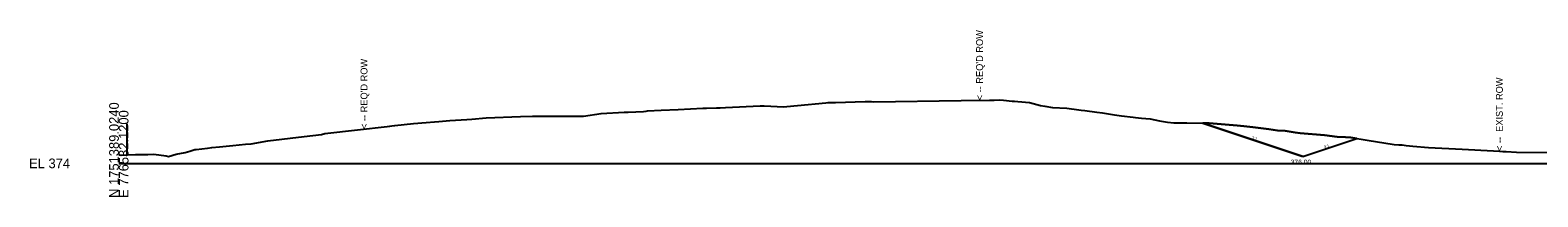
# Model space of a CAD drawing. Extents: x 776426 to 854588, y 1736205 to 1756790.
# Drawn here: x 805845.1 to 806281.9, y 1742205.1 to 1742253.4 of the extents above; entities that cross this region are included whole.
import ezdxf

# ---------------------------------------------------------------- set-up
doc = ezdxf.new("R2010")
doc.units = 0
for name, color, linetype in [('DTM CONTOURS_MAJOR_TX', 7, 'Continuous'), ('DTM_X_FLOW_ARROWS', 7, 'Continuous'), ('TRANS_EOP_PAVED', 7, 'Continuous'), ('XS_M_SHAPES_EARTHWORK', 7, 'Continuous'), ('XS_P_FINISHED_GRADE', 7, 'Continuous'), ('XS_P_ROW', 7, 'Continuous'), ('XS_P_TX_DCH', 7, 'Continuous'), ('XS_P_TX_FS_BS', 7, 'Continuous'), ('XS_X_ROW', 7, 'Continuous')]:
    doc.layers.add(name, color=color, linetype=linetype)

msp = doc.modelspace()

# ---------------------------------------------------------------- linework, layer by layer
at = {"layer": 'DTM CONTOURS_MAJOR_TX'}
msp.add_line((805870.79, 1742214.76), (806370.79, 1742214.76), dxfattribs=at)
at = {"layer": 'DTM_X_FLOW_ARROWS'}
msp.add_lwpolyline([(805870.79, 1742217.18), (805875.66, 1742217.33), (805879.19, 1742217.36), (805880.91, 1742217.4), (805884.47, 1742216.96), (805885.15, 1742216.79), (805887.37, 1742217.39), (805889.99, 1742217.89), (805891.36, 1742218.33), (805892.48, 1742218.7), (805892.78, 1742218.75), (805893.2, 1742218.8), (805896.48, 1742219.19), (805897.72, 1742219.4), (805899.96, 1742219.56), (805903.86, 1742219.95), (805907.54, 1742220.32), (805909.11, 1742220.44), (805914, 1742221.31), (805924.45, 1742222.5), (805929.49, 1742223.17), (805930.45, 1742223.38), (805939.91, 1742224.51), (805948.54, 1742225.4), (805949.34, 1742225.53), (805949.93, 1742225.59), (805950.79, 1742225.71), (805956.19, 1742226.31), (805957.45, 1742226.43), (805958.58, 1742226.5), (805963.49, 1742226.92), (805966.68, 1742227.15), (805971.61, 1742227.47), (805973.03, 1742227.54), (805977.21, 1742227.93), (805987.18, 1742228.38), (805990.64, 1742228.41), (805991.22, 1742228.41), (805991.83, 1742228.41), (805995.99, 1742228.41), (805997.85, 1742228.41), (806001.05, 1742228.4), (806005.42, 1742228.39), (806010.54, 1742229.22), (806017.2, 1742229.55), (806017.76, 1742229.58), (806018.37, 1742229.62), (806022.77, 1742229.82), (806023.56, 1742229.88), (806023.92, 1742229.96), (806027.93, 1742230.17), (806032.82, 1742230.38), (806039.99, 1742230.71), (806040.54, 1742230.73), (806041.07, 1742230.74), (806044, 1742230.84), (806045.03, 1742230.88), (806046.57, 1742230.97), (806056.6, 1742231.44), (806057.78, 1742231.43), (806063.51, 1742231.16), (806064.33, 1742231.25), (806067.44, 1742231.54), (806075.64, 1742232.31), (806076.28, 1742232.39), (806078.42, 1742232.43), (806087.04, 1742232.64), (806088.88, 1742232.65), (806089.42, 1742232.62), (806114.86, 1742232.93), (806123.1, 1742233.06), (806123.59, 1742233.08), (806124.4, 1742233.1), (806125.82, 1742233.14), (806127.11, 1742233.04), (806129.64, 1742232.82), (806130.28, 1742232.74), (806131.24, 1742232.64), (806134.67, 1742232.41), (806137.88, 1742231.57), (806139.08, 1742231.33), (806141.34, 1742230.94), (806145.45, 1742230.74), (806148.92, 1742230.3), (806149.6, 1742230.16), (806150.68, 1742230.07), (806154.14, 1742229.58), (806155.81, 1742229.36), (806159.31, 1742228.87), (806161.28, 1742228.58), (806164.73, 1742228.17), (806165.34, 1742228.09), (806167.11, 1742227.9), (806169.59, 1742227.68), (806172.29, 1742227.06), (806174.65, 1742226.69), (806176.51, 1742226.49), (806180.19, 1742226.48), (806185.03, 1742226.41), (806186, 1742226.43), (806186.39, 1742226.42), (806186.7, 1742226.38), (806194.84, 1742225.71), (806196.74, 1742225.56), (806199.38, 1742225.25), (806203.99, 1742224.66), (806206.54, 1742224.32), (806208.7, 1742224.2), (806211.63, 1742223.69), (806213.06, 1742223.55), (806220.14, 1742222.97), (806223.83, 1742222.47), (806226.21, 1742222.34), (806227.72, 1742222.27), (806232.53, 1742221.44), (806240.29, 1742220.24), (806241.66, 1742220.13), (806242.64, 1742220.09), (806243.74, 1742219.98), (806245.7, 1742219.75), (806250.28, 1742219.32), (806260.04, 1742218.85), (806269.06, 1742218.4), (806270.78, 1742218.33), (806271.79, 1742218.25), (806272.75, 1742218.21), (806275.76, 1742218.02), (806292.37, 1742217.87)], dxfattribs=at)
at = {"layer": 'TRANS_EOP_PAVED'}
msp.add_line((805873.14, 1742226.25), (805873.14, 1742217.25), dxfattribs=at)
msp.add_line((805873.14, 1742226.25), (805873.14, 1742217.25), dxfattribs=at)
at = {"layer": 'XS_M_SHAPES_EARTHWORK'}
msp.add_lwpolyline([(806213.82, 1742216.76), (806229.45, 1742221.97), (806227.72, 1742222.27), (806226.21, 1742222.34), (806223.83, 1742222.47), (806220.14, 1742222.97), (806213.06, 1742223.55), (806211.63, 1742223.69), (806208.7, 1742224.2), (806206.54, 1742224.32), (806203.99, 1742224.66), (806199.38, 1742225.25), (806196.74, 1742225.56), (806194.84, 1742225.71), (806186.7, 1742226.38), (806186.39, 1742226.42), (806186, 1742226.43), (806185.03, 1742226.41), (806184.87, 1742226.41)], close=True, dxfattribs=at)
at = {"layer": 'XS_P_FINISHED_GRADE'}
for q in [(806184.87, 1742226.41), (806229.45, 1742221.97)]:
    msp.add_line((806213.82, 1742216.76), q, dxfattribs=at)

# ---------------------------------------------------------------- texts
at = {"layer": 'DTM CONTOURS_MAJOR_TX'}
for s, p in [('N 1751389.0240', (805870.79, 1742204.76)), ('E 776532.1200', (805873.59, 1742204.76))]:
    msp.add_text(s, height=2.8, rotation=90, dxfattribs=at).set_placement(p)
msp.add_text('EL 374', height=2.8, dxfattribs=at).set_placement((805844.79, 1742213.36))
at = {"layer": 'XS_P_ROW'}
for p in [(806121.18, 1742233.02), (805942.83, 1742224.71)]:
    msp.add_text("< -- REQ'D ROW", height=2, rotation=90, dxfattribs=at).set_placement(p)
at = {"layer": 'XS_P_TX_DCH'}
msp.add_text('376.00', height=1.4, dxfattribs=at).set_placement((806210.34, 1742214.43))
at = {"layer": 'XS_P_TX_FS_BS'}
for rotation, p in [(341.5651, (806199.01, 1742221.91)), (18.4349, (806220.12, 1742219.09))]:
    msp.add_text('3:1', height=0.8, rotation=rotation, dxfattribs=at).set_placement(p)
at = {"layer": 'XS_X_ROW'}
msp.add_text('< --  EXIST. ROW', height=2, rotation=90, dxfattribs=at).set_placement((806271.79, 1742218.33))

doc.saveas('drawing.dxf')
